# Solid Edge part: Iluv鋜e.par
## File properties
Author: Türk
Template: iso part.par
Last saved by: Türk
Revision: 5
Application: Solid Edge
Accuracy: 0,990
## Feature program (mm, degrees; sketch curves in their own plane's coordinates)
base feature "unnamed BaseFeature 1"
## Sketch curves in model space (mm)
line (-293.9193, -735, -90) -> (293.9193, -735, -90)
line (217.6603, -735, 170) -> (-217.6603, -735, 170)
line (-341.3121, -735, -80) -> (-342.6532, -735, -80)
line (331.9534, -735, -69.05) -> (-331.9534, -735, -69.05)
arc centre (-293.9193, -735, -45) radius 45 from (-331.9534, -735, -69.05) through (-332.8801, -735, -67.5178) to (-333.7451, -735, -65.95)
line (333.7451, -735, -65.95) -> (-333.7451, -735, -65.95)
arc centre (293.9193, -735, -45) radius 45 from (333.7451, -735, -65.95) through (332.8801, -735, -67.5178) to (331.9534, -735, -69.05)
arc centre (-293.9193, -735, -45) radius 45 from (-320.1699, -735, -81.55) through (-322.1379, -735, -80.0529) to (-324.0207, -735, -78.45)
line (-320.1699, -735, -81.55) -> (320.1699, -735, -81.55)
arc centre (293.9193, -735, -45) radius 45 from (324.0207, -735, -78.45) through (322.1379, -735, -80.0529) to (320.1699, -735, -81.55)
line (324.0207, -735, -78.45) -> (-324.0207, -735, -78.45)
line (337.4118, -735, -56.55) -> (-337.4118, -735, -56.55)
arc centre (-293.9193, -735, -45) radius 45 from (-337.4118, -735, -56.55) through (-337.6098, -735, -55.7767) to (-337.7941, -735, -55)
line (-337.7941, -735, -53.45) -> (-337.7941, -735, -55)
line (337.7941, -735, -53.45) -> (-337.7941, -735, -53.45)
line (337.7941, -735, -55) -> (337.7941, -735, -53.45)
arc centre (293.9193, -735, -45) radius 45 from (337.7941, -735, -55) through (337.6098, -735, -55.7767) to (337.4118, -735, -56.55)
line (338.9193, -735, -44.05) -> (-338.9193, -735, -44.05)
line (338.9193, -735, -44.05) -> (338.9193, -735, -40.95)
line (338.9193, -735, -40.95) -> (-338.9193, -735, -40.95)
line (-338.9193, -735, -40.95) -> (-338.9193, -735, -44.05)
line (338.9193, -735, -28.45) -> (-338.9193, -735, -28.45)
line (-338.9193, -735, -31.55) -> (-338.9193, -735, -28.45)
line (338.9193, -735, -31.55) -> (-338.9193, -735, -31.55)
line (338.9193, -735, -31.55) -> (338.9193, -735, -28.45)
line (338.9193, -735, -19.05) -> (-338.9193, -735, -19.05)
line (338.9193, -735, -19.05) -> (338.9193, -735, -15.95)
line (338.9193, -735, -15.95) -> (-338.9193, -735, -15.95)
line (-338.9193, -735, -15.95) -> (-338.9193, -735, -19.05)
line (338.9193, -735, -6.55) -> (-338.9193, -735, -6.55)
line (338.9193, -735, -3.45) -> (338.9193, -735, -6.55)
line (-338.9193, -735, -3.45) -> (338.9193, -735, -3.45)
line (-338.9193, -735, -3.45) -> (-338.9193, -735, -6.55)
line (333.9898, -735, 9.05) -> (-333.9898, -735, 9.05)
line (333.9898, -735, 9.05) -> (335.2623, -735, 5.95)
line (-335.2623, -735, 5.95) -> (335.2623, -735, 5.95)
line (-335.2623, -735, 5.95) -> (-333.9898, -735, 9.05)
line (-329.4949, -735, 20) -> (-329.4949, -735, 18.45)
line (-329.4949, -735, 18.45) -> (329.4949, -735, 18.45)
line (329.4949, -735, 20) -> (329.4949, -735, 18.45)
line (328.8587, -735, 21.55) -> (329.4949, -735, 20)
line (-328.8587, -735, 21.55) -> (328.8587, -735, 21.55)
line (-328.8587, -735, 21.55) -> (-329.4949, -735, 20)
line (323.7276, -735, 34.05) -> (-323.7276, -735, 34.05)
line (325.0001, -735, 30.95) -> (323.7276, -735, 34.05)
line (-325.0001, -735, 30.95) -> (325.0001, -735, 30.95)
line (-325.0001, -735, 30.95) -> (-323.7276, -735, 34.05)
line (318.5965, -735, 46.55) -> (-318.5965, -735, 46.55)
line (319.2327, -735, 45) -> (318.5965, -735, 46.55)
line (319.2327, -735, 43.45) -> (319.2327, -735, 45)
line (-319.2327, -735, 43.45) -> (319.2327, -735, 43.45)
line (-319.2327, -735, 45) -> (-319.2327, -735, 43.45)
line (-319.2327, -735, 45) -> (-318.5965, -735, 46.55)
line (314.7379, -735, 55.95) -> (-314.7379, -735, 55.95)
line (314.7379, -735, 55.95) -> (313.4653, -735, 59.05)
line (313.4653, -735, 59.05) -> (-313.4653, -735, 59.05)
line (-313.4653, -735, 59.05) -> (-314.7379, -735, 55.95)
line (308.3342, -735, 71.55) -> (-308.3342, -735, 71.55)
line (308.3342, -735, 71.55) -> (308.9705, -735, 70)
line (308.9705, -735, 70) -> (308.9705, -735, 68.45)
line (-308.9705, -735, 68.45) -> (308.9705, -735, 68.45)
line (-308.9705, -735, 70) -> (-308.9705, -735, 68.45)
line (-308.9705, -735, 70) -> (-308.3342, -735, 71.55)
line (303.2031, -735, 84.05) -> (-303.2031, -735, 84.05)
line (304.4756, -735, 80.95) -> (303.2031, -735, 84.05)
line (-304.4756, -735, 80.95) -> (304.4756, -735, 80.95)
line (-304.4756, -735, 80.95) -> (-303.2031, -735, 84.05)
line (-298.7083, -735, 95) -> (-298.7083, -735, 93.45)
line (-298.7083, -735, 93.45) -> (298.7083, -735, 93.45)
line (298.7083, -735, 93.45) -> (298.7083, -735, 95)
line (298.072, -735, 96.55) -> (298.7083, -735, 95)
line (298.072, -735, 96.55) -> (-298.072, -735, 96.55)
line (-298.072, -735, 96.55) -> (-298.7083, -735, 95)
line (-294.2134, -735, 105.95) -> (294.2134, -735, 105.95)
line (294.2134, -735, 105.95) -> (292.9409, -735, 109.05)
line (292.9409, -735, 109.05) -> (-292.9409, -735, 109.05)
line (-292.9409, -735, 109.05) -> (-294.2134, -735, 105.95)
line (-288.4461, -735, 120) -> (-288.4461, -735, 118.45)
line (-288.4461, -735, 118.45) -> (288.4461, -735, 118.45)
line (288.4461, -735, 118.45) -> (288.4461, -735, 120)
line (288.4461, -735, 120) -> (287.9811, -735, 121.1327)
line (287.9811, -735, 121.1327) -> (287.8141, -735, 121.55)
line (287.8141, -735, 121.55) -> (-287.8141, -735, 121.55)
line (-287.8141, -735, 121.55) -> (-287.9811, -735, 121.1327)
line (-287.9811, -735, 121.1327) -> (-288.4461, -735, 120)
line (281.6923, -735, 134.05) -> (-281.6923, -735, 134.05)
arc centre (217.6603, -735, 95) radius 75 from (281.6923, -735, 134.05) through (282.606, -735, 132.5107) to (283.4827, -735, 130.95)
line (-283.4827, -735, 130.95) -> (283.4827, -735, 130.95)
arc centre (-217.6603, -735, 95) radius 75 from (-283.4827, -735, 130.95) through (-282.606, -735, 132.5107) to (-281.6923, -735, 134.05)
line (272.1359, -735, 146.55) -> (-272.1359, -735, 146.55)
arc centre (217.6603, -735, 95) radius 75 from (272.1359, -735, 146.55) through (272.8544, -735, 145.78) to (273.562, -735, 145)
line (273.562, -735, 145) -> (273.562, -735, 143.45)
line (-273.562, -735, 143.45) -> (273.562, -735, 143.45)
line (-273.562, -735, 145) -> (-273.562, -735, 143.45)
arc centre (-217.6603, -735, 95) radius 75 from (-273.562, -735, 145) through (-272.8544, -735, 145.78) to (-272.1359, -735, 146.55)
line (-256.6807, -735, 159.05) -> (256.6807, -735, 159.05)
arc centre (217.6603, -735, 95) radius 75 from (256.6807, -735, 159.05) through (259.0519, -735, 157.5439) to (261.3649, -735, 155.95)
line (-261.3649, -735, 155.95) -> (261.3649, -735, 155.95)
arc centre (-217.6603, -735, 95) radius 75 from (-261.3649, -735, 155.95) through (-259.0519, -735, 157.5439) to (-256.6807, -735, 159.05)
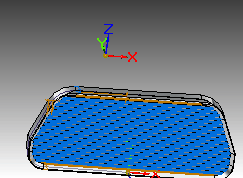
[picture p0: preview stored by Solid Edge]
